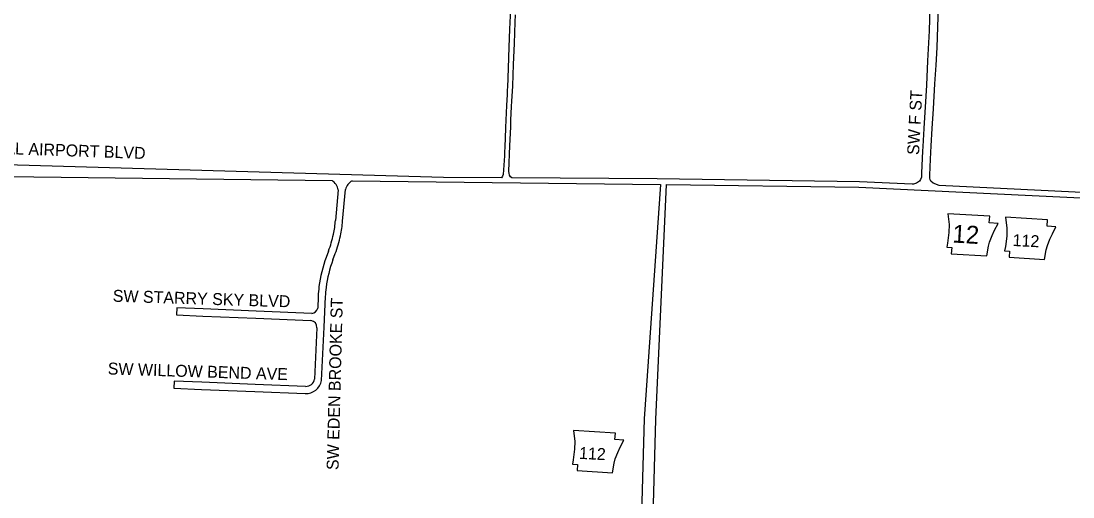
# Model space of a CAD drawing. Extents: x 0 to 712119, y 0 to 761125.
# Drawn here: x 655706 to 660107, y 734886 to 736879 of the extents above; entities that cross this region are included whole.
import ezdxf

# ---------------------------------------------------------------- set-up
doc = ezdxf.new("R2010")
doc.units = 0
for name, color, linetype in [('HWY signs', 7, 'Continuous'), ('PAVED ROADS', 7, 'Continuous'), ('street names', 7, 'Continuous')]:
    doc.layers.add(name, color=color, linetype=linetype)

msp = doc.modelspace()

# ---------------------------------------------------------------- linework, layer by layer
at = {"layer": 'HWY signs'}
for points in [[(659747.1, 735895.5), (659753.5, 735935.8), (659758.2, 735953.5), (659768.5, 735980.3), (659779.2, 736002.7), (659794, 736031.8), (659757, 736034), (659758.7, 736061.4), (659583.2, 736072), (659588.6, 736026.4), (659588.1, 735993.3), (659582.5, 735949), (659579.6, 735931.4), (659599.8, 735930.2), (659598.2, 735904.4)], [(659988.8, 735880.9), (659995.3, 735921.3), (660000, 735939), (660010.2, 735965.7), (660021, 735988.1), (660035.8, 736017.2), (659998.8, 736019.4), (660000.5, 736046.8), (659825, 736057.4), (659830.4, 736011.8), (659829.9, 735978.7), (659824.3, 735934.4), (659821.4, 735916.9), (659841.6, 735915.7), (659840, 735889.9)], [(658181, 734988.1), (658187.4, 735028.4), (658192.1, 735046.1), (658202.4, 735072.9), (658213.1, 735095.3), (658227.9, 735124.4), (658191, 735126.6), (658192.6, 735154), (658017.1, 735164.6), (658022.6, 735119), (658022, 735085.9), (658016.5, 735041.6), (658013.6, 735024), (658033.7, 735022.8), (658032.2, 734997)]]:
    msp.add_lwpolyline(points, close=True, dxfattribs=at)
at = {"layer": 'PAVED ROADS'}
for points in [[(657753.4, 736928.9), (657749.7, 736845.1), (657747, 736769.4), (657743.9, 736681.1), (657740.8, 736600.3), (657740.4, 736591.6), (657739.5, 736570.9), (657737.5, 736524.9), (657733.5, 736433.4), (657731.4, 736387.5), (657730.8, 736374.3), (657730.6, 736368.1), (657728.4, 736314.2), (657722.6, 736235.8), (657720.2, 736229), (657715.5, 736222), (657473, 736223.4), (653810.4, 736330.2)], [(659508, 736936.4), (659505.7, 736837.8), (659498.7, 736711.9), (659494.2, 736610.6), (659488.6, 736517.9), (659482.9, 736429.7), (659482.9, 736428.8), (659479.1, 736354.1), (659478.1, 736334.1), (659473.5, 736243.5), (659473.3, 736225.8), (659469.9, 736214.9), (659465, 736207.8), (659453.2, 736200.5), (659439.5, 736196.1), (659434.8, 736196.3), (659213.5, 736205.5), (658366.9, 736218.8), (657759, 736221.9), (657754, 736226.4), (657750.1, 736233.5), (657747.6, 736241.2), (657746.8, 736249.3), (657746.8, 736250.8), (657751.4, 736356.9), (657754.6, 736435.3), (657755.8, 736464.8), (657758.1, 736519.7), (657758.2, 736521.4), (657759.3, 736542.8), (657762.9, 736606.4), (657762.9, 736607.4), (657766.2, 736697.4), (657770.1, 736785.2), (657773.5, 736873.8), (657774.7, 736905.1)], [(661000, 736118.7), (659547.2, 736190.9), (659521.7, 736200.5), (659512.5, 736208.6), (659509.3, 736214.3), (659508.5, 736221.9), (659508.9, 736233.7), (659511.8, 736300), (659514.6, 736356.3), (659518.5, 736428.3), (659523.7, 736511.7), (659529.8, 736616.3), (659534.5, 736693.9), (659538.4, 736768.5), (659541.9, 736854.7), (659544.1, 736933.9)], [(655645, 736228.5), (655646.4, 736228.5), (657007.1, 736211.2)], [(657090.8, 736209.6), (658382, 736194), (658312.4, 735213.2), (658243, 732734.1)], [(658230.3, 731160.8), (658231.2, 731182.3), (658293, 732733), (658362.3, 735211.2), (658407, 736194.5), (659211, 736183.8), (661386.8, 736078.1), (661473, 736073.3), (661537.6, 736069.6), (661582.4, 736071.2), (661646.5, 736077.2), (661679.8, 736078.9), (661707.2, 736077.9), (661745.9, 736073.4), (661770, 736070.4), (661810.5, 736068), (662271.2, 736045.5), (662342.9, 736043)], [(657032.4, 736171.5), (657021.5, 736044)], [(657051.4, 736041.4), (657062.8, 736174)], [(656992.7, 735915.9), (656982.8, 735889.4)], [(657010.9, 735878.9), (657020.8, 735905.3)], [(656949, 735726.1), (656947, 735676.1)], [(656963.6, 735374.4), (656973.8, 735596.7), (656979, 735724.9)], [(656922.2, 735654.4), (656688.9, 735664.3), (656467.4, 735673.6), (656358.1, 735678.2), (656356.8, 735648.3), (656466.1, 735643.6), (656687.7, 735634.3), (656918.8, 735624.5)], [(656943.7, 735595.1), (656934.1, 735379.8)], [(656896.3, 735349.5), (656685.8, 735357.9), (656462.7, 735366.8), (656345.9, 735371.4), (656344.7, 735341.4), (656461.5, 735336.8), (656684.6, 735327.9), (656895.1, 735319.6)]]:
    msp.add_lwpolyline(points, dxfattribs=at)
for centre, radius, start, end in [((656977.9, 736164.7), 54.9, 7.0552, 57.9015), ((657122.7, 736155.7), 62.7, 120.6551, 163.0796), ((656562.6, 736083.3), 460.6, 347.8037, 355.1027), ((656562.6, 736083.3), 490.6, 347.8037, 355.1027), ((656475.1, 736102.2), 550.1, 340.2104, 347.8037), ((656475.7, 736102.1), 579.5, 340.1571, 347.8056), ((657465.2, 735704.3), 516.6, 159.002, 173.0243), ((657465.2, 735704.3), 486.7, 158.9709, 173.0231), ((657453.6, 735705.8), 505, 173.035, 177.693), ((657453.6, 735705.8), 475, 173.035, 177.693), ((656920.3, 735681.6), 27.2, 273.9537, 348.5249), ((656916.1, 735596.9), 27.7, 356.1145, 84.3013), ((656897.7, 735386.5), 67, 267.7231, 349.5807), ((656897.7, 735386.5), 37, 267.7231, 349.5807)]:
    msp.add_arc(centre, radius, start, end, dxfattribs=at)

# ---------------------------------------------------------------- texts
at = {"layer": 'HWY signs'}
for s, height, rotation, p in [('12', 75, 356.5521, (659601.1, 735951.8)), ('112', 50, 357.0105, (659854, 735937.2)), ('112', 50, 357.0105, (658039.7, 735046.1))]:
    msp.add_text(s, height=height, rotation=rotation, dxfattribs=at).set_placement(p)
at = {"layer": 'street names'}
for s, rotation, p in [('SW F ST', 86.9838, (659463.1, 736317)), ('SW REGIONAL AIRPORT BLVD', 357.9335, (655245.9, 736336.2)), ('SW STARRY SKY BLVD', 358.1607, (656089, 735703.9)), ('SW EDEN BROOKE ST', 88.5608, (657034.2, 734998.7)), ('SW WILLOW BEND AVE', 358.1607, (656068, 735399.4))]:
    msp.add_text(s, height=50, rotation=rotation, dxfattribs=at).set_placement(p)

doc.saveas('drawing.dxf')
